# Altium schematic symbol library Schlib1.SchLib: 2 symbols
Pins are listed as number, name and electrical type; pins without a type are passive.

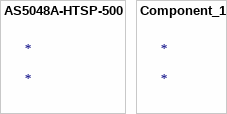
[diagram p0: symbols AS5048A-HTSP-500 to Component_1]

## AS5048A-HTSP-500
designator *
Rotary Position Sensor 5.5V/3.6V Digital Output 14-Pin TSSOP T/R; Manufacturer: ams; Manufacturer Part Number: AS5048A-HTSP-500; Max Supply Voltage: 5.5V; Min Supply Voltage: 3V; Operating Supply Current: 15mA; Output Current: 4mA; Output Type: PWM, SPI; Resolution: 1.75B; Sensing Method: Hall Effect

## Component_1
designator *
